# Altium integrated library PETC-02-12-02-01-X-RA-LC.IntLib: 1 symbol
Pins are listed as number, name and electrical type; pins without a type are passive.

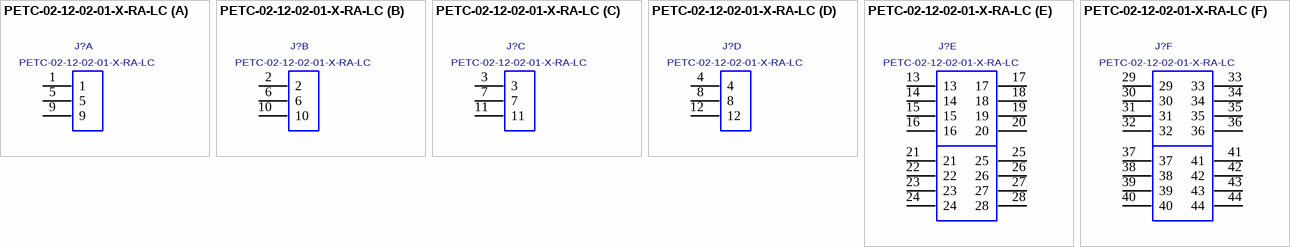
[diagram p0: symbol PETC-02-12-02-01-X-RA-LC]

## PETC-02-12-02-01-X-RA-LC
designator J?
RIGHT ANGLE POWER TERMINAL.; MANUFACTURER: SAMTEC
footprint PETC-02-12-02-01-X-RA-LC
part A pins: 1, 5, 9
part B pins: 2, 6, 10
part C pins: 3, 7, 11
part D pins: 4, 8, 12
part E pins: 13, 14, 15, 16, 17, 18, 19, 20, 21, 22, 23, 24, 25, 26, 27, 28
part F pins: 29, 30, 31, 32, 33, 34, 35, 36, 37, 38, 39, 40, 41, 42, 43, 44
